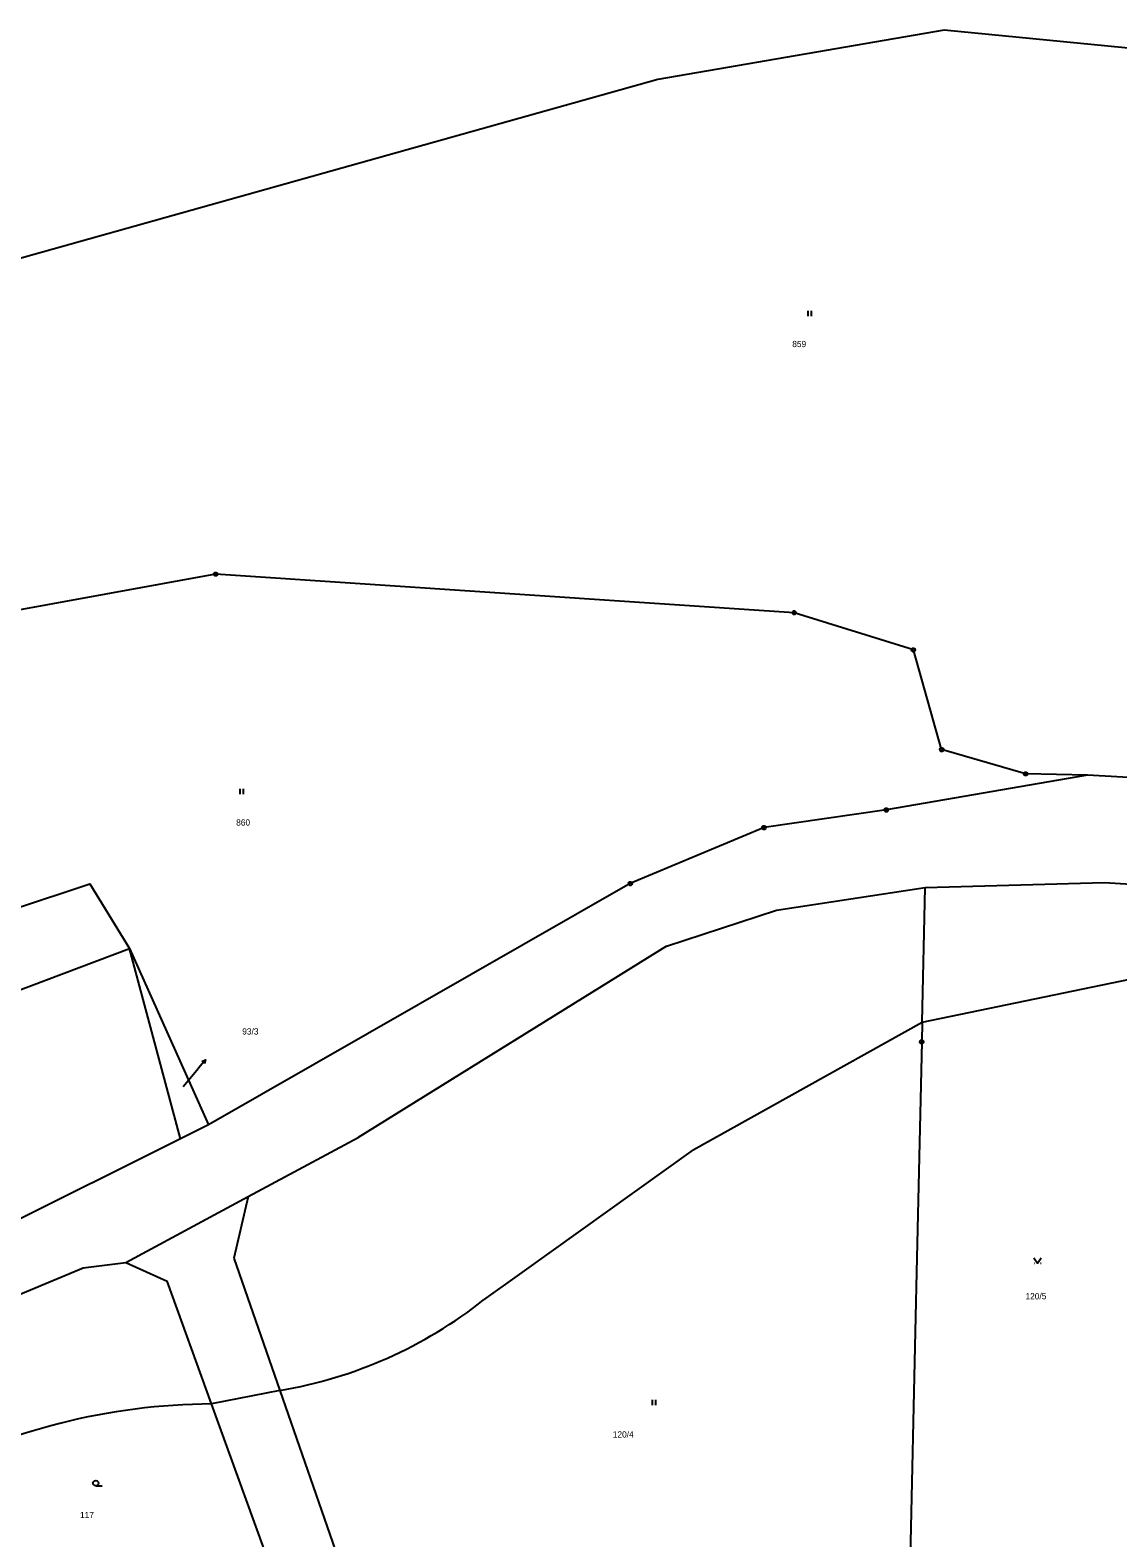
# Model space of a CAD drawing. Extents: x -871430 to -870620, y -1010094 to -1009649.
# Drawn here: x -870823.3 to -870749.2, y -1009821.3 to -1009718.6 of the extents above; entities that cross this region are included whole.
import ezdxf

# ---------------------------------------------------------------- set-up
doc = ezdxf.new("R2010")
doc.units = 0
for name, color, linetype in [('Vrstva 1', 7, 'Continuous'), ('Vrstva 2', 7, 'Continuous'), ('Vrstva 3', 7, 'Continuous'), ('Vrstva 4', 7, 'Continuous'), ('Vrstva 7', 7, 'Continuous'), ('Vrstva 8', 7, 'Continuous')]:
    doc.layers.add(name, color=color, linetype=linetype)

msp = doc.modelspace()

# ---------------------------------------------------------------- linework, layer by layer
at = {"layer": 'Vrstva 1'}
for p, q in [((-870761.01, -1009718.63), (-870780.52, -1009721.98)), ((-870738.27, -1009720.84), (-870761.01, -1009718.63)), ((-870780.52, -1009721.98), (-870853.46, -1009742.46)), ((-870810.65, -1009755.67), (-870830.08, -1009759.22)), ((-870771.24, -1009758.3), (-870810.65, -1009755.67)), ((-870763.12, -1009760.83), (-870771.24, -1009758.3)), ((-870761.2, -1009767.62), (-870763.12, -1009760.83)), ((-870755.47, -1009769.27), (-870761.2, -1009767.62)), ((-870751.26, -1009769.35), (-870764.96, -1009771.73)), ((-870751.26, -1009769.35), (-870755.47, -1009769.27)), ((-870733.71, -1009770.39), (-870751.26, -1009769.35)), ((-870764.96, -1009771.73), (-870773.29, -1009772.93)), ((-870773.29, -1009772.93), (-870782.4, -1009776.74)), ((-870782.4, -1009776.74), (-870811.13, -1009793.16)), ((-870772.44, -1009778.56), (-870762.31, -1009777.01)), ((-870762.52, -1009786.18), (-870762.31, -1009777.01)), ((-870762.31, -1009777.01), (-870750.1, -1009776.66)), ((-870750.1, -1009776.66), (-870730.64, -1009777.93)), ((-870779.93, -1009781), (-870772.44, -1009778.56)), ((-870838.41, -1009789.46), (-870816.52, -1009781.15)), ((-870813.03, -1009794.11), (-870816.52, -1009781.15)), ((-870816.52, -1009781.15), (-870811.13, -1009793.16)), ((-870779.93, -1009781), (-870800.93, -1009794.02)), ((-870762.52, -1009786.18), (-870762.55, -1009787.51)), ((-870762.55, -1009787.51), (-870762.9, -1009803.19)), ((-870811.13, -1009793.16), (-870813.03, -1009794.11)), ((-870813.03, -1009794.11), (-870825.19, -1009800.18)), ((-870808.42, -1009798.05), (-870800.93, -1009794.02)), ((-870816.77, -1009802.54), (-870808.42, -1009798.05)), ((-870808.42, -1009798.05), (-870809.4, -1009802.24)), ((-870819.66, -1009802.91), (-870816.77, -1009802.54)), ((-870816.77, -1009802.54), (-870813.94, -1009803.81)), ((-870809.4, -1009802.24), (-870806.27, -1009811.26)), ((-870834.21, -1009808.96), (-870819.66, -1009802.91)), ((-870762.9, -1009803.19), (-870762.97, -1009806.25)), ((-870810.92, -1009812.17), (-870813.94, -1009803.81)), ((-870762.97, -1009806.25), (-870763.36, -1009823.67)), ((-870806.27, -1009811.26), (-870802.3, -1009822.69)), ((-870806.57, -1009824.19), (-870810.92, -1009812.17))]:
    msp.add_line(p, q, dxfattribs=at)
msp.add_lwpolyline([(-870849.95, -1009786.94), (-870819.21, -1009776.75), (-870816.52, -1009781.15)], dxfattribs=at)
at = {"layer": 'Vrstva 3'}
for p, q in [((-870770.305, -1009737.735), (-870770.305, -1009738.11)), ((-870770.055, -1009738.11), (-870770.055, -1009737.735)), ((-870808.985, -1009770.285), (-870808.985, -1009770.66)), ((-870808.735, -1009770.66), (-870808.735, -1009770.285)), ((-870754.898, -1009802.59), (-870754.872, -1009802.59)), ((-870754.448, -1009802.59), (-870754.422, -1009802.59)), ((-870780.905, -1009811.885), (-870780.905, -1009812.26)), ((-870780.655, -1009812.26), (-870780.655, -1009811.885))]:
    msp.add_line(p, q, dxfattribs=at)
for points in [[(-870754.91, -1009802.215), (-870754.66, -1009802.59), (-870754.41, -1009802.215)], [(-870818.81, -1009817.75), (-870818.905, -1009817.725), (-870818.972, -1009817.655), (-870818.998, -1009817.562), (-870818.972, -1009817.47), (-870818.905, -1009817.4), (-870818.81, -1009817.375), (-870818.715, -1009817.4), (-870818.648, -1009817.47), (-870818.622, -1009817.562), (-870818.648, -1009817.655), (-870818.715, -1009817.725), (-870818.81, -1009817.75), (-870818.372, -1009817.75)]]:
    msp.add_lwpolyline(points, dxfattribs=at)
at = {"layer": 'Vrstva 4'}
for p, q in [((-870762.52, -1009786.18), (-870747.71, -1009783.12)), ((-870778.11, -1009794.87), (-870762.52, -1009786.18)), ((-870778.11, -1009794.87), (-870789.95, -1009803.34)), ((-870789.95, -1009803.34), (-870792.39, -1009805.09)), ((-870806.27, -1009811.26), (-870810.92, -1009812.17))]:
    msp.add_line(p, q, dxfattribs=at)
for centre, radius, start, end in [((-870811.426, -1009780.964), 30.732, 279.6584, 308.27423), ((-870810.614, -1009855.369), 43.2, 90.40568, 118.09695)]:
    msp.add_arc(centre, radius, start, end, dxfattribs=at)
at = {"layer": 'Vrstva 7'}
for p in [(-870812.85, -1009790.56), (-870811.329, -1009788.745)]:
    msp.add_line(p, (-870811.81, -1009789.32), dxfattribs=at)
msp.add_lwpolyline([(-870811.585, -1009788.856), (-870811.329, -1009788.745), (-870811.393, -1009789.017)], dxfattribs=at)
at = {"layer": 'Vrstva 8'}
for p, q in [((-870810.662, -1009755.67), (-870810.638, -1009755.67)), ((-870771.252, -1009758.3), (-870771.228, -1009758.3)), ((-870763.132, -1009760.83), (-870763.108, -1009760.83)), ((-870761.212, -1009767.62), (-870761.188, -1009767.62)), ((-870755.482, -1009769.27), (-870755.458, -1009769.27)), ((-870764.972, -1009771.73), (-870764.948, -1009771.73)), ((-870773.302, -1009772.93), (-870773.278, -1009772.93)), ((-870782.412, -1009776.74), (-870782.388, -1009776.74)), ((-870762.562, -1009787.51), (-870762.538, -1009787.51))]:
    msp.add_line(p, q, dxfattribs=at)
for points in [[(-870810.612, -1009755.55), (-870810.55, -1009755.598), (-870810.525, -1009755.67), (-870810.55, -1009755.742), (-870810.612, -1009755.79), (-870810.688, -1009755.79), (-870810.75, -1009755.742), (-870810.775, -1009755.67), (-870810.75, -1009755.598), (-870810.688, -1009755.55), (-870810.612, -1009755.55)], [(-870771.202, -1009758.18), (-870771.14, -1009758.228), (-870771.115, -1009758.3), (-870771.14, -1009758.372), (-870771.202, -1009758.42), (-870771.278, -1009758.42), (-870771.34, -1009758.372), (-870771.365, -1009758.3), (-870771.34, -1009758.228), (-870771.278, -1009758.18), (-870771.202, -1009758.18)], [(-870763.082, -1009760.71), (-870763.02, -1009760.758), (-870762.995, -1009760.83), (-870763.02, -1009760.902), (-870763.082, -1009760.95), (-870763.158, -1009760.95), (-870763.22, -1009760.902), (-870763.245, -1009760.83), (-870763.22, -1009760.758), (-870763.158, -1009760.71), (-870763.082, -1009760.71)], [(-870761.162, -1009767.5), (-870761.1, -1009767.548), (-870761.075, -1009767.62), (-870761.1, -1009767.692), (-870761.162, -1009767.74), (-870761.237, -1009767.74), (-870761.3, -1009767.692), (-870761.325, -1009767.62), (-870761.3, -1009767.548), (-870761.237, -1009767.5), (-870761.162, -1009767.5)], [(-870755.432, -1009769.15), (-870755.37, -1009769.198), (-870755.345, -1009769.27), (-870755.37, -1009769.342), (-870755.432, -1009769.39), (-870755.508, -1009769.39), (-870755.57, -1009769.342), (-870755.595, -1009769.27), (-870755.57, -1009769.198), (-870755.508, -1009769.15), (-870755.432, -1009769.15)], [(-870764.922, -1009771.61), (-870764.86, -1009771.658), (-870764.835, -1009771.73), (-870764.86, -1009771.802), (-870764.922, -1009771.85), (-870764.997, -1009771.85), (-870765.06, -1009771.802), (-870765.085, -1009771.73), (-870765.06, -1009771.658), (-870764.997, -1009771.61), (-870764.922, -1009771.61)], [(-870773.253, -1009772.81), (-870773.19, -1009772.858), (-870773.165, -1009772.93), (-870773.19, -1009773.003), (-870773.253, -1009773.05), (-870773.328, -1009773.05), (-870773.39, -1009773.003), (-870773.415, -1009772.93), (-870773.39, -1009772.858), (-870773.328, -1009772.81), (-870773.253, -1009772.81)], [(-870782.362, -1009776.62), (-870782.3, -1009776.668), (-870782.275, -1009776.74), (-870782.3, -1009776.812), (-870782.362, -1009776.86), (-870782.438, -1009776.86), (-870782.5, -1009776.812), (-870782.525, -1009776.74), (-870782.5, -1009776.668), (-870782.438, -1009776.62), (-870782.362, -1009776.62)], [(-870762.513, -1009787.39), (-870762.45, -1009787.438), (-870762.425, -1009787.51), (-870762.45, -1009787.582), (-870762.513, -1009787.63), (-870762.588, -1009787.63), (-870762.65, -1009787.582), (-870762.675, -1009787.51), (-870762.65, -1009787.438), (-870762.588, -1009787.39), (-870762.513, -1009787.39)]]:
    msp.add_lwpolyline(points, dxfattribs=at)

# ---------------------------------------------------------------- texts
at = {"layer": 'Vrstva 2'}
for s, height, p in [('859', 0.425, (-870771.367, -1009740.212)), ('860', 0.425, (-870809.245, -1009772.792)), ('93/3', 0.025, (-870812.847, -1009790.56)), ('120/5', 0.425, (-870755.483, -1009805.05)), ('120/4', 0.425, (-870783.592, -1009814.46)), ('117', 0.425, (-870819.882, -1009819.95))]:
    msp.add_text(s, height=height, dxfattribs=at).set_placement(p)
at = {"layer": 'Vrstva 7'}
msp.add_text('93/3', height=0.425, dxfattribs=at).set_placement((-870808.831, -1009787.02))

doc.saveas('drawing.dxf')
